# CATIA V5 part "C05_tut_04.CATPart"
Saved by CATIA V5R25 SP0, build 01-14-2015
Part number: Part1
Bounding box of the stored display mesh (mm): x -150 to 0, y -16 to 75, z 0 to 85
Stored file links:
  E:\ashutosh\Academics\Catia\CATIA V5-6R2013_partfiles\Tutorials_ver_2\C05_tut_04.CATPart
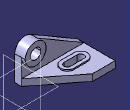
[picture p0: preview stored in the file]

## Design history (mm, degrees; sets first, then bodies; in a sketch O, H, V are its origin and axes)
Body1 (main body)
  Sketch1 on xy-plane, origin (0, 0, 0), H (1, 0, 0), V (0, 1, 0)
    line L1 (0, 0) -> (-150, 0)
    line L2 (-150, 0) -> (-150, 75)
    line L3 (-150, 75) -> (-96, 75)
    line L4 (-96, 75) -> (0, 0)
    length L2 = 75
    length L3 = 54
    length L1 = 150
    vertical: L2 V
    horizontal: L3 H, L1 H
  Pad1: profile Sketch1, direction (0, 0, 1), length 16
  Sketch2 on end face of Pad1, origin (0, 0, 16), H (1, 0, 0), V (0, 1, 0)
    construction line L1 (-114, 28) -> (-82, 28)
    point P1 (-114, 28)
    line L2 (-114, 44) -> (-82, 44)
    line L3 (-82, 12) -> (-114, 12)
    arc A1 centre (-82, 28) radius 16 from (-82, 44) to (-82, 12) cw
    arc A2 centre (-114, 28) radius 16 from (-114, 12) to (-114, 44) cw
    reference projected line E1 (-150, 0) -> (0, 0) from edge [face of Pad1 from Sketch1.L1 | end face of Pad1]
    reference projected line E2 (-150, 75) -> (-150, 0) from edge [face of Pad1 from Sketch1.L2 | end face of Pad1]
    distance L1 L2 = 16
    distance L3 E1 = 12
    length L2 = 32
    distance P1 E2 = 36
    horizontal: L1 H
    tangency: A1 L2, A2 L2, A1 L3, A2 L3
  Pad2: profile Sketch2, direction (0, 0, 1), length 3
  Sketch3 on face of Pad1 from Sketch1.L1, origin (0, 0, 0), H (1, 0, 0), V (0, 0, 1)
    line L1 (0, 0) -> (0, 60)
    arc A1 centre (-25, 60) radius 25 from (0, 60) to (-37.6005, 81.5923) ccw
    line L2 (-37.6005, 81.5923) -> (-150, 16)
    line L3 (-150, 16) -> (-150, 0)
    point P5 (-150, 0)
    line L4 (-150, 0) -> (0, 0)
    reference projected line E1 (-150, 0) -> (-150, 16) from edge [face of Pad1 from Sketch1.L1 | face of Pad1 from Sketch1.L2]
    radius A1 = 25
    length L1 = 60
    length L3 = 16
    vertical: L1 V, L3 V
    tangency: A1 L1, L2 A1
    coincidence: P5 H, L3 E1
    horizontal: L4 H
  Pad3: profile Sketch3, direction (0, -1, 0), length 16
  Sketch4 on start face of Pad3, origin (0, 0, 0), H (-1, 0, 0), V (0, 0, 1)
    circle A1 centre (25, 60) radius 25
    reference projected arc E1 centre (25, 60) radius 25 from (37.6005, 81.5923) to (0, 60) ccw from edge [start face of Pad3 | face of Pad3 from Sketch3.A1]
    reference projected arc E2 centre (25, 60) radius 25 from (37.6005, 81.5923) to (0, 60) ccw from edge [start face of Pad3 | face of Pad3 from Sketch3.A1]
    concentricity: A1 E1
    coincidence: A1 E2
  Pad4: profile Sketch4, direction (0, 1, 0), length 9
  Sketch5 on end face of Pad4, origin (0, 9, 0), H (-1, 0, 0), V (0, 0, 1)
    circle A1 centre (25, 60) radius 12.5
    reference projected circle E1 centre (25, 60) radius 25 from edge [face of Pad4 from Sketch4.A1 | end face of Pad4]
    radius A1 = 12.5
    concentricity: A1 E1
  Pocket1: profile Sketch5, direction (0, -1, 0), through (limit type 3)
  Sketch6 on end face of Pad2, origin (0, 0, 19), H (1, 0, 0), V (0, 1, 0)
    construction line L1 (-114, 28) -> (-82, 28)
    line L2 (-114, 36) -> (-82, 36)
    line L3 (-82, 20) -> (-114, 20)
    arc A1 centre (-82, 28) radius 8 from (-82, 36) to (-82, 20) cw
    arc A2 centre (-114, 28) radius 8 from (-114, 20) to (-114, 36) cw
    reference projected arc E1 centre (-114, 28) radius 16 from (-114, 44) to (-114, 12) ccw from edge [face of Pad2 from Sketch2.A2 | end face of Pad2]
    reference projected arc E2 centre (-82, 28) radius 16 from (-82, 12) to (-82, 44) ccw from edge [face of Pad2 from Sketch2.A1 | end face of Pad2]
    distance L2 L3 = 16
    horizontal: L1 H
    tangency: A1 L2, A2 L2, A1 L3, A2 L3
    concentricity: A2 E1, A1 E2
  Pocket2: profile Sketch6, direction (0, 0, -1), through (limit type 3)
